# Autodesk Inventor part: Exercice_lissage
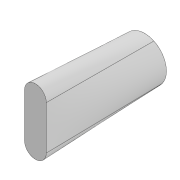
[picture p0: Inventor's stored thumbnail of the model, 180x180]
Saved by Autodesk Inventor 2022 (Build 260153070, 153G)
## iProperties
Created: 2021-06
Part Number: Exercice_lissage
Material: Générique
Document SubType Name: Modeling
Designer: Fabian
Density: 1 g/cm^3
Appearance: Par défaut
Author: Fabian
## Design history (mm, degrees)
node "Plan de construction1"
sketch "Esquisse1"
  geometry: C1 r 10 at (0, 0); 1 further point
  constraints: 1 centre point, 1 coincident
  dimensions: "d5" = 20 diameter of C1
sketch "Esquisse2"
  geometry: L1 (0, 10)-(0, -10); L2 (-5, 10)-(-5, -10); L3 (5, -10)-(5, 10); A1 r 5 centre (0, 10) between (5, 10) and (-5, 10); A2 r 5 centre (0, -10) between (-5, -10) and (5, -10); 1 further point
  constraints: 8 end point, 4 point on circle, 4 tangent, 2 centre point, 1 midpoint, 1 parallel, 1 vertical
  dimensions: "d14" = 20 distance of L1.start L1.end; "d15" = 5 radius of A1
feature "Lissage3" dims "d30" = 0, "d31" = 90 deg, "d32" = 0, "d33" = 90 deg
node "Solide3"
